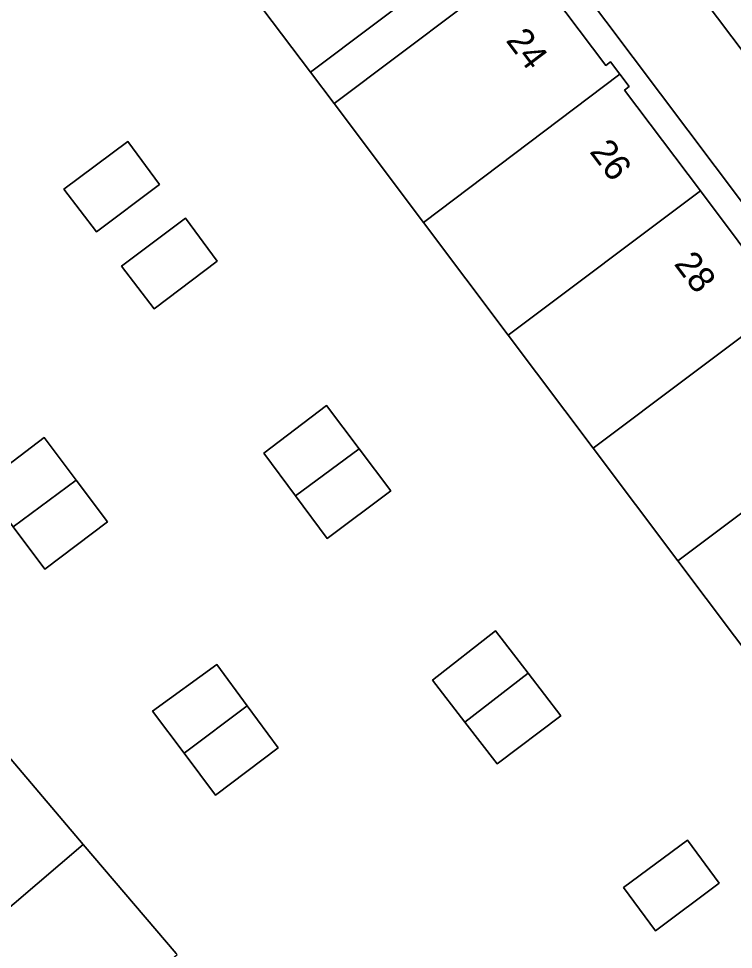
# Model space of a CAD drawing. Extents: x 160377 to 161131, y 383938 to 384853.
# Drawn here: x 160560.31 to 160587.58, y 384619.15 to 384654.67 of the extents above; entities that cross this region are included whole.
import ezdxf

# ---------------------------------------------------------------- set-up
doc = ezdxf.new("R2010")
doc.units = 0
for name, color, linetype in [('IMGEO_Erf', 7, 'Continuous'), ('IMGEO_Groenvoorziening', 7, 'Continuous'), ('IMGEO_Pand', 7, 'Continuous'), ('IMGEO_Pand_nummerreeks', 7, 'Continuous'), ('IMGEO_Voetgangersgebied_open', 7, 'Continuous')]:
    doc.layers.add(name, color=color, linetype=linetype)

msp = doc.modelspace()

# ---------------------------------------------------------------- linework, layer by layer
at = {"layer": 'IMGEO_Erf'}
for points in [[(160603.494, 384626.95), (160531.839, 384722.221)], [(160587.217, 384614.645), (160593.711, 384619.536), (160595.355, 384620.775), (160595.375, 384620.79), (160592.113, 384625.131), (160588.706, 384629.665), (160585.467, 384633.975), (160582.227, 384638.285), (160578.993, 384642.588), (160575.759, 384646.891), (160572.348, 384651.43), (160571.441, 384652.625), (160568.164, 384656.977), (160564.888, 384661.328), (160561.612, 384665.679), (160558.335, 384670.03)], [(160578.76, 384658.133), (160571.441, 384652.625), (160572.348, 384651.43), (160579.665, 384656.941), (160582.715, 384652.889), (160582.892, 384653.02), (160583.248, 384652.55), (160583.603, 384652.079), (160583.422, 384651.949), (160586.32, 384648.095), (160589.204, 384644.259)], [(160559.235, 384627.312), (160562.78, 384623.153), (160566.325, 384618.994)]]:
    msp.add_lwpolyline(points, dxfattribs=at)
for points in [[(160564.48, 384649.984), (160565.683, 384648.343), (160563.279, 384646.531), (160562.041, 384648.167)], [(160566.676, 384647.059), (160567.884, 384645.422), (160565.485, 384643.592), (160564.236, 384645.229)], [(160569.668, 384638.088), (160572.063, 384639.907), (160573.305, 384638.257), (160574.518, 384636.647), (160572.078, 384634.829), (160570.873, 384636.459)], [(160561.285, 384638.69), (160562.505, 384637.061), (160563.696, 384635.471), (160561.312, 384633.66), (160560.109, 384635.273), (160558.905, 384636.885)], [(160578.507, 384631.312), (160579.746, 384629.689), (160580.991, 384628.06), (160578.57, 384626.228), (160577.335, 384627.828), (160576.1, 384629.427)], [(160567.877, 384630.022), (160569.036, 384628.445), (160570.212, 384626.844), (160567.828, 384625.032), (160566.625, 384626.636), (160565.421, 384628.239)], [(160583.382, 384621.512), (160585.835, 384623.322), (160587.033, 384621.676), (160584.604, 384619.863)]]:
    msp.add_lwpolyline(points, close=True, dxfattribs=at)
at = {"layer": 'IMGEO_Groenvoorziening'}
msp.add_lwpolyline([(160557.616, 384707.68), (160553.827, 384709.767), (160550.857, 384704.721), (160549.861, 384704.03), (160584.207, 384658.391), (160596.343, 384642.27), (160596.599, 384643.678)], dxfattribs=at)
at = {"layer": 'IMGEO_Pand'}
for points in [[(160578.76, 384658.133), (160575.485, 384662.485), (160568.164, 384656.977), (160571.441, 384652.625)], [(160583.248, 384652.55), (160582.892, 384653.02), (160582.715, 384652.889), (160579.665, 384656.941), (160572.348, 384651.43), (160575.759, 384646.891)], [(160586.32, 384648.095), (160583.422, 384651.949), (160583.603, 384652.079), (160583.248, 384652.55), (160575.759, 384646.891), (160578.993, 384642.588)], [(160562.041, 384648.167), (160563.279, 384646.531), (160565.683, 384648.343), (160564.48, 384649.984)], [(160589.733, 384643.922), (160589.374, 384644.4), (160589.204, 384644.259), (160586.32, 384648.095), (160578.993, 384642.588), (160582.227, 384638.285)], [(160564.236, 384645.229), (160565.485, 384643.592), (160567.884, 384645.422), (160566.676, 384647.059)], [(160592.795, 384639.483), (160589.923, 384643.302), (160590.092, 384643.444), (160589.733, 384643.922), (160582.227, 384638.285), (160585.467, 384633.975)], [(160573.305, 384638.257), (160572.063, 384639.907), (160569.668, 384638.088), (160570.873, 384636.459)], [(160596.236, 384635.288), (160595.883, 384635.76), (160595.702, 384635.617), (160592.795, 384639.483), (160585.467, 384633.975), (160588.706, 384629.665)], [(160558.905, 384636.885), (160560.109, 384635.273), (160562.505, 384637.061), (160561.285, 384638.69)], [(160573.305, 384638.257), (160570.873, 384636.459), (160572.078, 384634.829), (160574.518, 384636.647)], [(160562.505, 384637.061), (160560.109, 384635.273), (160561.312, 384633.66), (160563.696, 384635.471)], [(160579.746, 384629.689), (160578.507, 384631.312), (160576.1, 384629.427), (160577.335, 384627.828)], [(160565.421, 384628.239), (160566.625, 384626.636), (160569.036, 384628.445), (160567.877, 384630.022)], [(160579.746, 384629.689), (160577.335, 384627.828), (160578.57, 384626.228), (160580.991, 384628.06)], [(160569.036, 384628.445), (160566.625, 384626.636), (160567.828, 384625.032), (160570.212, 384626.844)], [(160562.78, 384623.153), (160559.235, 384627.312), (160552.287, 384621.39), (160555.646, 384617.452), (160555.833, 384617.232)], [(160583.382, 384621.512), (160584.604, 384619.863), (160587.033, 384621.676), (160585.835, 384623.322)], [(160566.361, 384618.952), (160566.325, 384618.994), (160562.78, 384623.153), (160555.833, 384617.232), (160556.83, 384616.065), (160559.348, 384613.089), (160559.422, 384613.011), (160559.441, 384613.028)]]:
    msp.add_lwpolyline(points, close=True, dxfattribs=at)
at = {"layer": 'IMGEO_Voetgangersgebied_open'}
for points in [[(160539.968, 384717.188), (160535.283, 384723.428), (160534.832, 384724.029), (160531.839, 384722.221), (160603.494, 384626.95), (160604.071, 384626.182), (160600.544, 384623.533), (160605.23, 384617.306), (160607.339, 384614.528), (160608.482, 384613.028), (160611.972, 384615.646), (160634.758, 384585.358), (160653.945, 384599.94), (160649.862, 384602.565), (160648.502, 384603.464), (160618.749, 384622.917), (160617.41, 384623.8), (160615.335, 384625.155)], [(160604.773, 384631.072), (160604.303, 384631.697), (160599.161, 384638.527), (160596.343, 384642.27), (160584.207, 384658.391), (160549.861, 384704.03), (160544.079, 384711.713)]]:
    msp.add_lwpolyline(points, dxfattribs=at)

# ---------------------------------------------------------------- texts
at = {"layer": 'IMGEO_Pand_nummerreeks'}
for s, rotation, p in [('24', 306.967, (160578.874, 384653.834)), ('26', 306.9384, (160582.068, 384649.59)), ('28', 306.9384, (160585.288, 384645.309))]:
    msp.add_text(s, height=1, rotation=rotation, dxfattribs=at).set_placement(p)

doc.saveas('drawing.dxf')
